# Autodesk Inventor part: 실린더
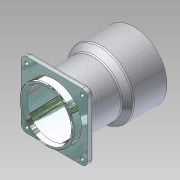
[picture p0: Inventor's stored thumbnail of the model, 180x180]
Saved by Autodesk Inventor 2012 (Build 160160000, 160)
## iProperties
Manager: KYOUNG IL JANG
Company: 한국ATC센터
Created: 2012-10
Part Number: 실린더
Material: 기본값
Document SubType Name: 모델링
Density: 1 g/cm^3
Checked By: KYOUNG IL JANG
Vendor: CBT Solutions
Designer: KYOUNG IL JANG
Author: KYOUNG IL JANG
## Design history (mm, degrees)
sketch "스케치1"
  geometry: L1 (0, 0)-(0, 112); L2 (30, 0)-(30, 112); L3 (30, 112)-(42.5, 112); L4 (42.5, 112)-(42.5, 69); L5 (42.5, 69)-(35, 61); L6 (35, 61)-(35, 0); L7 (35, 0)-(30, 0)
  constraints: 14 end point, 4 parallel, 2 point on line, 1 perpendicular, 1 vertical
  dimensions: "d0" = 112 distance of L1.start L1.end; "d2" = 85 diameter of L4 L1; "d3" = 70 diameter of L6 L1; "d5" = 60 diameter of L2 L1; "d33" = 43 distance of L3.end L4.end; "d34" = 51 distance from line of L3 L5.end
revolve "회전1" stored, may be unused: angle "d6" = 90 deg
node "작업 평면1"
sketch "스케치2"
  geometry: L1 (-42.5, 42.5)-(42.5, 42.5); L2 (42.5, 42.5)-(42.5, -42.5); L3 (42.5, -42.5)-(-42.5, -42.5); L4 (-42.5, -42.5)-(-42.5, 42.5); C1 r 35 at (0, 0) reference; 3 further points
  constraints: 8 end point, 2 midpoint, 2 parallel, 2 perpendicular, 1 horizontal, 1 horizontal alignment, 1 vertical alignment
  dimensions: "d8" = 85 distance of L1.end L2.end
extrude "돌출1" join sketch "스케치2" distance "d9" = 8; taper "d10" = 0 deg
fillet "모깎기1" dims "d11" = 7, "d12" = 3
sketch "스케치3"
  geometry: L1 (0, 42.5)-(0, 30); 4 further points
  constraints: 2 end point, 2 vertical alignment, 1 midpoint, 1 point on line, 1 vertical, 2 other
hole "구멍1" sketch "스케치3" at (0, 36.25) diameter "d14" = 4.134; stored, may be unused: countersink angle "d18" = 90 deg, drill point angle "d20" = 118 deg; dims "d15" = 12, "d16" = 4, "d17" = 2, "d19" = 15
sketch "스케치4"
  geometry: C1 r 1.621 at (35.5, -35.5) reference; C2 r 1.621 at (35.5, 35.5) reference; C3 r 1.621 at (-35.5, -35.5) reference; C4 r 1.621 at (-35.5, 35.5) reference; 1 further point
hole "구멍2" sketch "스케치4" at (35.5, 35.5), (35.5, -35.5), (-35.5, -35.5), (-35.5, 35.5) diameter "d26" = 4.5; stored, may be unused: countersink angle "d30" = 90 deg, drill point angle "d32" = 118 deg; dims "d27" = 12, "d28" = 8, "d29" = 4.4, "d31" = 15
chamfer "모따기1" distance "d35" = 5; stored, may be unused: second distance "d36" = 2, angle "d37" = 20 deg
chamfer "모따기2" distance "d38" = 1; stored, may be unused: second distance "d39" = 2, angle "d40" = 20 deg
node "솔리드1"
pattern_circular "원형 패턴1" dims angle "d22" = 360 deg
node "참조1"
node "참조2"
node "참조3"
node "참조4"
other parameters: "KFactor" = 4.4
